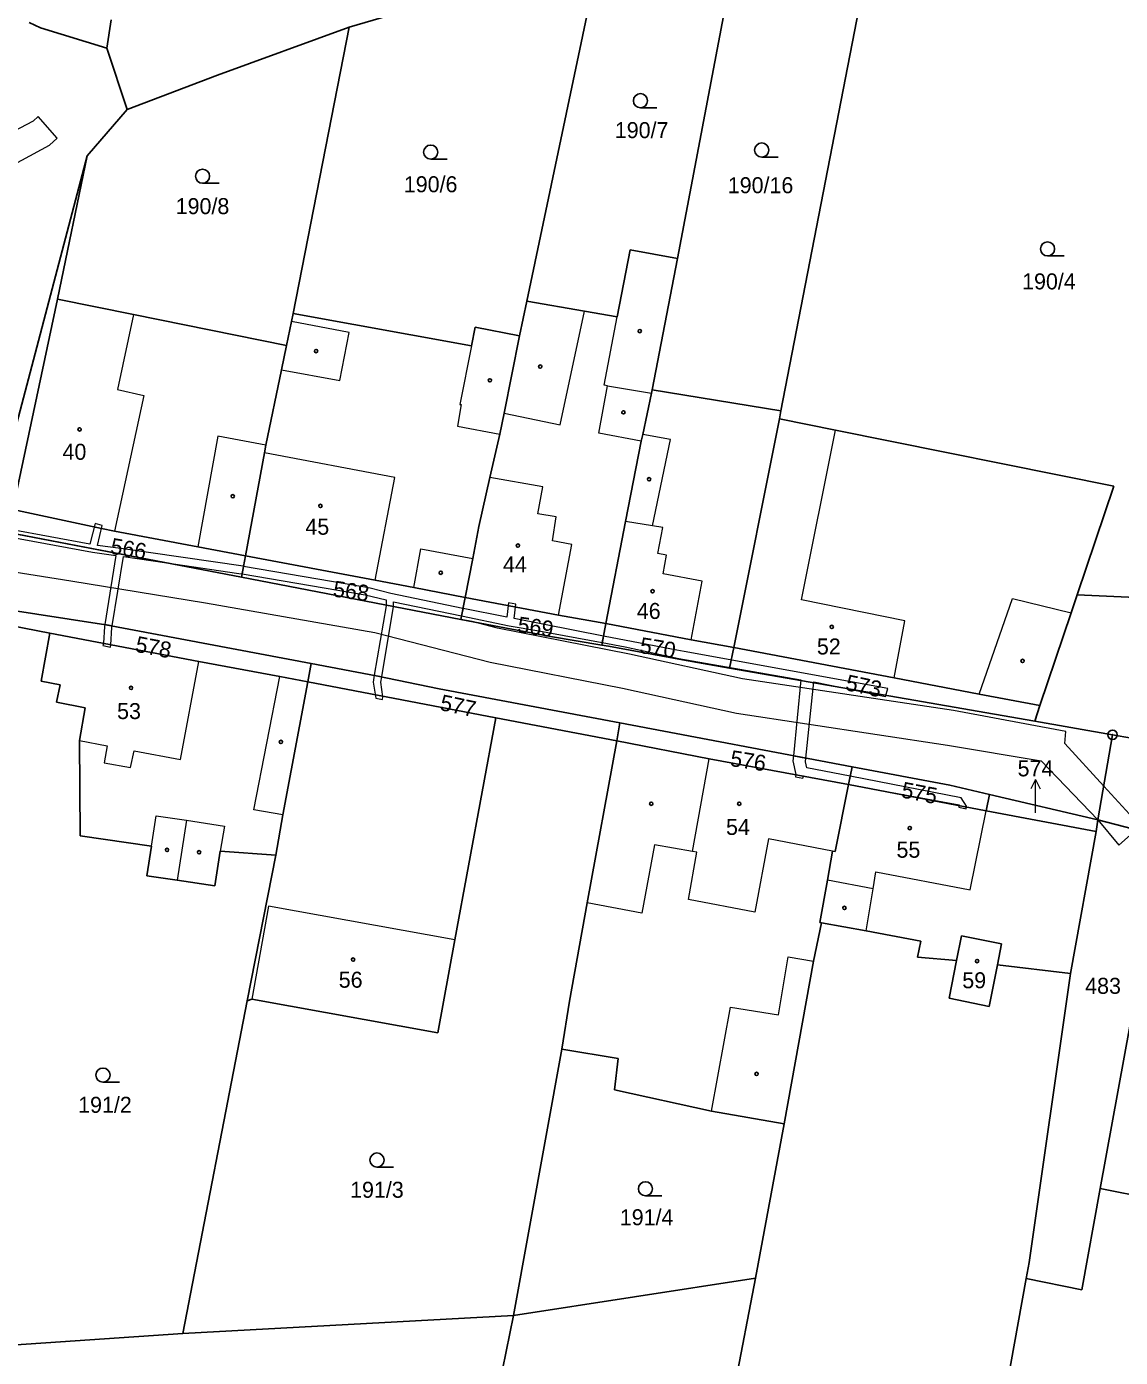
# Model space of a CAD drawing. Extents: x -769392 to -767038, y -1018329 to -1015269.
# Drawn here: x -768383.8 to -768267.7, y -1016351.8 to -1016210.5 of the extents above; entities that cross this region are included whole.
import ezdxf
from ezdxf.enums import TextEntityAlignment as Align

# ---------------------------------------------------------------- set-up
doc = ezdxf.new("R2010")
doc.units = 0
doc.header["$LTSCALE"] = 0.68
for name, color, linetype, lineweight in [('1', 7, 'Continuous', 25), ('13', 7, 'Continuous', 13), ('3', 7, 'Continuous', 25), ('4', 7, 'Continuous', 13), ('5', 7, 'Continuous', 25), ('7', 7, 'Continuous', 13), ('8', 7, 'Continuous', 25)]:
    doc.layers.add(name, color=color, linetype=linetype, lineweight=lineweight)
doc.layers.add('2', color=7, linetype='Continuous')

msp = doc.modelspace()

# ---------------------------------------------------------------- linework, layer by layer
at = {"layer": '1'}
for p, q in [((-768308.37, -1016201.54), (-768314.74, -1016235.08)), ((-768322.98, -1016202.72), (-768349.59, -1016210.55)), ((-768330.71, -1016239.64), (-768322.98, -1016202.72)), ((-768294.39, -1016202.9), (-768303.76, -1016251.27)), ((-768382.33, -1016210.62), (-768383.54, -1016210.03)), ((-768374.85, -1016209.77), (-768375.29, -1016212.76)), ((-768375.29, -1016212.76), (-768382.33, -1016210.62)), ((-768349.59, -1016210.55), (-768363.55, -1016215.62)), ((-768355.52, -1016240.92), (-768349.59, -1016210.55)), ((-768373.13, -1016219.28), (-768375.29, -1016212.76)), ((-768363.55, -1016215.62), (-768373.13, -1016219.28)), ((-768373.13, -1016219.28), (-768377.38, -1016224.21)), ((-768377.38, -1016224.21), (-768387.81, -1016263.79)), ((-768380.52, -1016239.41), (-768377.38, -1016224.21)), ((-768319.76, -1016234.16), (-768321.12, -1016241.28)), ((-768314.74, -1016235.08), (-768319.76, -1016234.16)), ((-768314.74, -1016235.08), (-768317.41, -1016249.05)), ((-768385.26, -1016261.73), (-768380.52, -1016239.41)), ((-768380.52, -1016239.41), (-768372.48, -1016241.04)), ((-768331.5, -1016243.31), (-768330.71, -1016239.64)), ((-768324.62, -1016240.68), (-768330.71, -1016239.64)), ((-768372.48, -1016241.04), (-768356.22, -1016244.34)), ((-768355.69, -1016241.78), (-768355.52, -1016240.92)), ((-768355.52, -1016240.92), (-768336.6, -1016244.38)), ((-768321.12, -1016241.28), (-768324.62, -1016240.68)), ((-768356.22, -1016244.34), (-768355.69, -1016241.78)), ((-768336.6, -1016244.38), (-768336.21, -1016242.38)), ((-768336.21, -1016242.38), (-768331.5, -1016243.31)), ((-768356.22, -1016244.34), (-768356.75, -1016246.91)), ((-768331.5, -1016243.31), (-768333.14, -1016251.52)), ((-768356.75, -1016246.91), (-768358.42, -1016254.92)), ((-768317.48, -1016249.4), (-768318.43, -1016253.78)), ((-768317.41, -1016249.05), (-768317.48, -1016249.4)), ((-768303.76, -1016251.27), (-768317.41, -1016249.05)), ((-768303.76, -1016251.27), (-768303.92, -1016252.12)), ((-768333.14, -1016251.52), (-768333.58, -1016253.73)), ((-768303.92, -1016252.12), (-768308.77, -1016276.41)), ((-768303.92, -1016252.12), (-768297.96, -1016253.32)), ((-768333.58, -1016253.73), (-768334.64, -1016258.34)), ((-768318.43, -1016253.78), (-768318.58, -1016254.49)), ((-768297.96, -1016253.32), (-768268.44, -1016259.26)), ((-768358.42, -1016254.92), (-768358.57, -1016255.72)), ((-768318.58, -1016254.49), (-768320.27, -1016263.01)), ((-768358.57, -1016255.72), (-768360.58, -1016266.67)), ((-768334.64, -1016258.34), (-768335.81, -1016263.56)), ((-768268.44, -1016259.26), (-768272.33, -1016270.82)), ((-768375.87, -1016263.76), (-768385.26, -1016261.73)), ((-768374.47, -1016264.03), (-768375.87, -1016263.76)), ((-768365.62, -1016265.71), (-768374.47, -1016264.03)), ((-768335.81, -1016263.56), (-768336.46, -1016266.94)), ((-768320.27, -1016263.01), (-768322.34, -1016273.86)), ((-768361, -1016268.94), (-768385.75, -1016264.19)), ((-768360.58, -1016266.67), (-768365.62, -1016265.71)), ((-768361, -1016268.94), (-768360.58, -1016266.67)), ((-768346.82, -1016269.26), (-768360.58, -1016266.67)), ((-768336.46, -1016266.94), (-768337.26, -1016271.07)), ((-768337.71, -1016273.41), (-768361, -1016268.94)), ((-768342.7, -1016270.04), (-768346.82, -1016269.26)), ((-768337.26, -1016271.07), (-768342.7, -1016270.04)), ((-768337.71, -1016273.41), (-768337.26, -1016271.07)), ((-768327.37, -1016272.95), (-768337.26, -1016271.07)), ((-768272.97, -1016272.72), (-768272.33, -1016270.82)), ((-768272.33, -1016270.82), (-768252.88, -1016271.66)), ((-768386.61, -1016272.27), (-768375.4, -1016273.98)), ((-768381.35, -1016274.89), (-768387.13, -1016273.73)), ((-768375.4, -1016273.98), (-768353.62, -1016278.09)), ((-768328.21, -1016275.23), (-768337.71, -1016273.41)), ((-768322.34, -1016273.86), (-768327.37, -1016272.95)), ((-768322.78, -1016276.14), (-768322.34, -1016273.86)), ((-768313.27, -1016275.57), (-768322.34, -1016273.86)), ((-768276.27, -1016282.57), (-768272.97, -1016272.72)), ((-768381.35, -1016274.89), (-768382.25, -1016279.96)), ((-768365.54, -1016277.87), (-768381.35, -1016274.89)), ((-768322.78, -1016276.14), (-768328.21, -1016275.23)), ((-768322.07, -1016276.26), (-768322.78, -1016276.14)), ((-768314.21, -1016277.72), (-768322.07, -1016276.26)), ((-768308.77, -1016276.41), (-768313.27, -1016275.57)), ((-768308.77, -1016276.41), (-768309.21, -1016278.59)), ((-768308.77, -1016276.41), (-768291.74, -1016279.61)), ((-768356.95, -1016279.48), (-768365.54, -1016277.87)), ((-768353.62, -1016278.09), (-768353.98, -1016280.04)), ((-768353.62, -1016278.09), (-768346.71, -1016279.39)), ((-768309.21, -1016278.59), (-768314.21, -1016277.72)), ((-768353.98, -1016280.04), (-768356.95, -1016279.48)), ((-768346.71, -1016279.39), (-768340.04, -1016280.77)), ((-768276.82, -1016284.22), (-768309.21, -1016278.59)), ((-768291.74, -1016279.61), (-768282.71, -1016281.35)), ((-768382.25, -1016279.96), (-768380.26, -1016280.37)), ((-768380.26, -1016280.37), (-768380.63, -1016282.2)), ((-768356.61, -1016294.15), (-768353.98, -1016280.04)), ((-768353.98, -1016280.04), (-768334.01, -1016283.86)), ((-768340.04, -1016280.77), (-768320.84, -1016284.4)), ((-768380.63, -1016282.2), (-768377.59, -1016282.81)), ((-768282.71, -1016281.35), (-768276.27, -1016282.57)), ((-768377.59, -1016282.81), (-768378.2, -1016286.27)), ((-768334.01, -1016283.86), (-768338.35, -1016307.43)), ((-768321.19, -1016286.32), (-768334.01, -1016283.86)), ((-768276.82, -1016284.22), (-768276.27, -1016282.57)), ((-768320.84, -1016284.4), (-768321.19, -1016286.32)), ((-768320.84, -1016284.4), (-768296.2, -1016289.06)), ((-768268.57, -1016285.66), (-768276.82, -1016284.22)), ((-768378.2, -1016286.27), (-768378.13, -1016296.38)), ((-768321.19, -1016286.32), (-768324.32, -1016303.49)), ((-768311.36, -1016288.22), (-768321.19, -1016286.32)), ((-768268.57, -1016285.66), (-768270.12, -1016294.69)), ((-768220.34, -1016294.37), (-768268.57, -1016285.66)), ((-768296.58, -1016290.95), (-768311.36, -1016288.22)), ((-768296.2, -1016289.06), (-768296.58, -1016290.95)), ((-768296.2, -1016289.06), (-768285.82, -1016291.02)), ((-768298, -1016298.06), (-768296.58, -1016290.95)), ((-768281.99, -1016293.72), (-768296.58, -1016290.95)), ((-768285.82, -1016291.02), (-768281.64, -1016292)), ((-768281.64, -1016292), (-768281.99, -1016293.72)), ((-768281.64, -1016292), (-768270.12, -1016294.69)), ((-768270.3, -1016295.94), (-768281.99, -1016293.72)), ((-768357.37, -1016298.45), (-768356.61, -1016294.15)), ((-768270.3, -1016295.94), (-768270.12, -1016294.69)), ((-768259.39, -1016297.5), (-768270.12, -1016294.69)), ((-768378.13, -1016296.38), (-768370.54, -1016297.49)), ((-768273.03, -1016311), (-768270.3, -1016295.94)), ((-768370.54, -1016297.49), (-768371.05, -1016300.65)), ((-768363.83, -1016301.69), (-768363.25, -1016298.02)), ((-768363.25, -1016298.02), (-768357.37, -1016298.45)), ((-768298.82, -1016301.09), (-768298.27, -1016298.01)), ((-768298.27, -1016298.01), (-768298, -1016298.06)), ((-768360.39, -1016313.91), (-768357.37, -1016298.45)), ((-768371.05, -1016300.65), (-768367.84, -1016301.11)), ((-768367.84, -1016301.11), (-768363.83, -1016301.69)), ((-768299.62, -1016305.58), (-768298.82, -1016301.09)), ((-768324.32, -1016303.49), (-768326.18, -1016313.96)), ((-768299.46, -1016305.61), (-768300.3, -1016309.68)), ((-768299.46, -1016305.61), (-768299.62, -1016305.58)), ((-768294.72, -1016306.48), (-768299.46, -1016305.61)), ((-768288.9, -1016307.57), (-768294.72, -1016306.48)), ((-768338.35, -1016307.43), (-768340.17, -1016317.32)), ((-768289.26, -1016309.26), (-768288.9, -1016307.57)), ((-768284.59, -1016306.99), (-768285.12, -1016309.64)), ((-768280.37, -1016307.87), (-768284.59, -1016306.99)), ((-768280.79, -1016310.1), (-768280.37, -1016307.87)), ((-768285.12, -1016309.64), (-768289.26, -1016309.26)), ((-768300.3, -1016309.68), (-768303.43, -1016326.96)), ((-768285.12, -1016309.64), (-768285.9, -1016313.61)), ((-768281.66, -1016314.5), (-768280.79, -1016310.1)), ((-768273.03, -1016311), (-768280.79, -1016310.1)), ((-768277.41, -1016341.69), (-768273.03, -1016311)), ((-768266.08, -1016312.93), (-768269.88, -1016333.83)), ((-768367.21, -1016349.21), (-768360.39, -1016313.91)), ((-768359.9, -1016313.74), (-768360.39, -1016313.91)), ((-768340.17, -1016317.32), (-768359.9, -1016313.74)), ((-768326.18, -1016313.96), (-768327.01, -1016319.05)), ((-768285.9, -1016313.61), (-768281.66, -1016314.5)), ((-768327.01, -1016319.05), (-768332.13, -1016347.3)), ((-768321.03, -1016320.03), (-768327.01, -1016319.05)), ((-768321.41, -1016323.34), (-768321.03, -1016320.03)), ((-768311.13, -1016325.63), (-768321.41, -1016323.34)), ((-768303.43, -1016326.96), (-768311.13, -1016325.63)), ((-768306.44, -1016343.34), (-768303.43, -1016326.96)), ((-768136.07, -1016360.95), (-768269.88, -1016333.83)), ((-768277.72, -1016343.38), (-768277.41, -1016341.69)), ((-768332.13, -1016347.3), (-768306.44, -1016343.34)), ((-768306.44, -1016343.34), (-768314.31, -1016383.77)), ((-768291.49, -1016419.17), (-768277.72, -1016343.38)), ((-768332.13, -1016347.3), (-768367.21, -1016349.21)), ((-768346.82, -1016419.68), (-768332.13, -1016347.3)), ((-768367.21, -1016349.21), (-768389.26, -1016350.71))]:
    msp.add_line(p, q, dxfattribs=at)
msp.add_lwpolyline([(-768277.72, -1016343.38), (-768271.84, -1016344.58), (-768269.88, -1016333.83)], dxfattribs=at)
at = {"layer": '13'}
for points in [[(-768388.12, -1016226.71), (-768381.36, -1016223.05), (-768380.55, -1016222.33), (-768382.57, -1016220.03), (-768383.12, -1016220.51), (-768385.18, -1016221.63)], [(-768265.62, -1016295.35), (-768269.5, -1016291.1), (-768273.62, -1016286.59), (-768273.53, -1016285.32), (-768285.46, -1016283.1), (-768307.82, -1016279.73), (-768319.82, -1016277.09), (-768333.82, -1016274.33), (-768336.54, -1016273.63), (-768337.71, -1016273.41), (-768361, -1016268.94), (-768369.19, -1016267.37), (-768384.81, -1016264.37), (-768387.74, -1016263.85), (-768388.8, -1016263.83), (-768395.26, -1016264.06), (-768395.51, -1016264.07), (-768399.68, -1016264.48), (-768411.09, -1016265.88), (-768414.99, -1016266.32), (-768422.34, -1016267.16), (-768438.59, -1016268.98), (-768453.04, -1016270.15)], [(-768449.1, -1016273.07), (-768429.05, -1016271.47), (-768417.15, -1016270.23), (-768402.63, -1016268.55), (-768392.04, -1016267.45), (-768388.19, -1016267.54), (-768385.13, -1016268.37), (-768379.1, -1016269.33), (-768364.82, -1016271.66), (-768346.84, -1016274.82), (-768334.63, -1016277.94), (-768320.58, -1016280.72), (-768308.49, -1016283.37), (-768286.07, -1016286.75), (-768276.15, -1016288.44), (-768270.12, -1016294.69), (-768266.07, -1016295.75)]]:
    msp.add_lwpolyline(points, dxfattribs=at)
for points in [[(-768388.54, -1016263.82), (-768386.79, -1016264.01), (-768385.83, -1016264.62), (-768376.82, -1016266.29), (-768374.34, -1016266.62), (-768375.51, -1016273.96), (-768375.4, -1016273.98), (-768374.73, -1016274.11), (-768373.54, -1016266.73), (-768369.19, -1016267.37), (-768385.75, -1016264.19), (-768387.81, -1016263.79)], [(-768386.47, -1016263.27), (-768387.64, -1016263.14), (-768387.81, -1016263.79), (-768385.75, -1016264.19), (-768369.19, -1016267.37), (-768361.27, -1016268.53), (-768360.93, -1016268.59), (-768360.79, -1016267.78), (-768360.84, -1016267.77), (-768373.79, -1016265.88), (-768376.3, -1016265.55), (-768375.77, -1016263.43), (-768376.53, -1016263.24), (-768377.1, -1016265.43), (-768385.53, -1016263.86)], [(-768360.93, -1016268.59), (-768347.88, -1016270.79), (-768345.66, -1016271.35), (-768345.66, -1016271.96), (-768346.91, -1016279.35), (-768346.71, -1016279.39), (-768346.11, -1016279.51), (-768344.86, -1016272.04), (-768344.86, -1016271.53), (-768337.64, -1016273.04), (-768337.49, -1016272.26), (-768337.53, -1016272.25), (-768345.17, -1016270.65), (-768347.36, -1016270.1), (-768348.14, -1016269.94), (-768360.79, -1016267.78)], [(-768332.61, -1016274.09), (-768329.46, -1016274.62), (-768322.73, -1016275.88), (-768322.59, -1016275.18), (-768332.05, -1016273.32), (-768331.88, -1016271.8), (-768332.66, -1016271.65), (-768332.84, -1016273.17), (-768337.49, -1016272.26), (-768337.64, -1016273.04)], [(-768374.75, -1016274.26), (-768374.73, -1016274.11), (-768375.51, -1016273.96), (-768375.54, -1016274.17), (-768375.64, -1016275.95), (-768375.7, -1016276.2), (-768374.92, -1016276.35), (-768374.86, -1016276.11)], [(-768322.73, -1016275.88), (-768320.3, -1016276.33), (-768314.59, -1016277.58), (-768301.66, -1016279.82), (-768302.43, -1016287.88), (-768301.1, -1016288.13), (-768300.27, -1016280.04), (-768292.65, -1016281.59), (-768292.41, -1016280.74), (-768314.04, -1016276.83), (-768314.82, -1016276.68), (-768322.59, -1016275.18)], [(-768346.21, -1016280.09), (-768346.11, -1016279.51), (-768346.71, -1016279.39), (-768346.91, -1016279.35), (-768347.03, -1016280.09), (-768346.73, -1016281.78), (-768346.05, -1016281.91), (-768346, -1016281.63)], [(-768302.48, -1016288.41), (-768302.17, -1016289.88), (-768302.2, -1016290.13), (-768301.42, -1016290.28), (-768301.37, -1016290.03), (-768296.58, -1016290.95), (-768296.4, -1016290.07), (-768301.02, -1016289.18), (-768301.14, -1016288.55), (-768301.1, -1016288.13), (-768302.43, -1016287.88)], [(-768284.88, -1016293.36), (-768284.1, -1016293.51), (-768284.05, -1016293.25), (-768284.65, -1016292.34), (-768296.4, -1016290.07), (-768296.58, -1016290.95), (-768284.85, -1016293.09)], [(-768267.89, -1016297.39), (-768266.07, -1016295.75), (-768270.12, -1016294.69)]]:
    msp.add_lwpolyline(points, close=True, dxfattribs=at)
at = {"layer": '3'}
for p, q in [((-768318.663, -1016219.09), (-768316.913, -1016219.09)), ((-768340.923, -1016224.55), (-768339.173, -1016224.55)), ((-768305.803, -1016224.33), (-768304.053, -1016224.33)), ((-768365.133, -1016227.11), (-768363.383, -1016227.11)), ((-768275.463, -1016234.83), (-768273.713, -1016234.83)), ((-768375.703, -1016322.54), (-768373.953, -1016322.54)), ((-768346.623, -1016331.56), (-768344.873, -1016331.56)), ((-768318.133, -1016334.61), (-768316.383, -1016334.61))]:
    msp.add_line(p, q, dxfattribs=at)
for centre in [(-768318.6629, -1016218.3398), (-768340.9229, -1016223.7998), (-768305.8029, -1016223.5798), (-768365.1329, -1016226.3598), (-768275.4629, -1016234.0798), (-768375.7029, -1016321.7898), (-768346.6229, -1016330.8098), (-768318.1329, -1016333.8598)]:
    msp.add_circle(centre, 0.75, dxfattribs=at)
at = {"layer": '4'}
for p, q in [((-768372.48, -1016241.04), (-768374.17, -1016249.02)), ((-768327.18, -1016252.75), (-768324.62, -1016240.68)), ((-768322.51, -1016248.55), (-768321.12, -1016241.28)), ((-768349.59, -1016242.95), (-768355.69, -1016241.78)), ((-768350.58, -1016248.06), (-768349.59, -1016242.95)), ((-768336.6, -1016244.38), (-768337.82, -1016250.59)), ((-768356.75, -1016246.91), (-768350.58, -1016248.06)), ((-768322.17, -1016248.6), (-768322.51, -1016248.55)), ((-768371.37, -1016249.63), (-768374.47, -1016264.03)), ((-768374.17, -1016249.02), (-768371.37, -1016249.63)), ((-768323.09, -1016253.65), (-768322.17, -1016248.6)), ((-768322.17, -1016248.6), (-768317.48, -1016249.4)), ((-768337.68, -1016250.61), (-768338.08, -1016252.89)), ((-768337.82, -1016250.59), (-768337.68, -1016250.61)), ((-768333.14, -1016251.52), (-768327.18, -1016252.75)), ((-768363.5, -1016253.96), (-768365.62, -1016265.71)), ((-768358.42, -1016254.92), (-768363.5, -1016253.96)), ((-768338.08, -1016252.89), (-768333.58, -1016253.73)), ((-768318.58, -1016254.49), (-768323.09, -1016253.65)), ((-768315.48, -1016254.3), (-768318.43, -1016253.78)), ((-768301.59, -1016271.34), (-768297.96, -1016253.32)), ((-768317.38, -1016263.47), (-768315.48, -1016254.3)), ((-768344.74, -1016258.34), (-768358.57, -1016255.72)), ((-768346.82, -1016269.26), (-768344.74, -1016258.34)), ((-768329.02, -1016259.32), (-768334.64, -1016258.34)), ((-768329.54, -1016262.22), (-768329.02, -1016259.32)), ((-768327.62, -1016262.54), (-768329.54, -1016262.22)), ((-768327.99, -1016265.06), (-768327.62, -1016262.54)), ((-768317.38, -1016263.47), (-768320.27, -1016263.01)), ((-768316.3, -1016263.65), (-768317.38, -1016263.47)), ((-768316.82, -1016266.43), (-768316.3, -1016263.65)), ((-768325.95, -1016265.45), (-768327.99, -1016265.06)), ((-768327.37, -1016272.95), (-768325.95, -1016265.45)), ((-768342.7, -1016270.04), (-768341.96, -1016265.91)), ((-768341.96, -1016265.91), (-768336.46, -1016266.94)), ((-768315.9, -1016266.61), (-768316.82, -1016266.43)), ((-768316.27, -1016268.58), (-768315.9, -1016266.61)), ((-768312.13, -1016269.36), (-768316.27, -1016268.58)), ((-768313.27, -1016275.57), (-768312.13, -1016269.36)), ((-768282.71, -1016281.35), (-768279.18, -1016271.18)), ((-768279.18, -1016271.18), (-768272.97, -1016272.72)), ((-768290.6, -1016273.55), (-768301.59, -1016271.34)), ((-768291.74, -1016279.61), (-768290.6, -1016273.55)), ((-768367.46, -1016288.29), (-768365.54, -1016277.87)), ((-768359.68, -1016293.64), (-768356.95, -1016279.48)), ((-768378.2, -1016286.27), (-768375.25, -1016286.84)), ((-768375.25, -1016286.84), (-768375.59, -1016288.63)), ((-768372.79, -1016289.15), (-768372.4, -1016287.37)), ((-768372.4, -1016287.37), (-768367.46, -1016288.29)), ((-768375.59, -1016288.63), (-768372.79, -1016289.15)), ((-768313.15, -1016298.05), (-768311.36, -1016288.22)), ((-768356.61, -1016294.15), (-768359.68, -1016293.64)), ((-768283.69, -1016302.12), (-768281.99, -1016293.72)), ((-768370.54, -1016297.49), (-768370.05, -1016294.27)), ((-768370.05, -1016294.27), (-768366.83, -1016294.74)), ((-768366.83, -1016294.74), (-768367.84, -1016301.11)), ((-768366.83, -1016294.74), (-768362.82, -1016295.35)), ((-768362.82, -1016295.35), (-768363.25, -1016298.02)), ((-768317.17, -1016297.33), (-768318.51, -1016304.59)), ((-768313.15, -1016298.05), (-768317.17, -1016297.33)), ((-768305.07, -1016296.7), (-768306.52, -1016304.49)), ((-768298.27, -1016298.01), (-768305.07, -1016296.7)), ((-768313.58, -1016303.16), (-768312.67, -1016298.14)), ((-768312.67, -1016298.14), (-768313.15, -1016298.05)), ((-768293.98, -1016302.03), (-768293.69, -1016300.21)), ((-768293.69, -1016300.21), (-768283.69, -1016302.12)), ((-768293.98, -1016302.03), (-768298.82, -1016301.09)), ((-768294.72, -1016306.48), (-768293.98, -1016302.03)), ((-768318.51, -1016304.59), (-768324.32, -1016303.49)), ((-768306.52, -1016304.49), (-768313.58, -1016303.16)), ((-768358.14, -1016303.86), (-768359.9, -1016313.74)), ((-768338.35, -1016307.43), (-768358.14, -1016303.86)), ((-768304, -1016315.4), (-768302.98, -1016309.24)), ((-768302.98, -1016309.24), (-768300.3, -1016309.68)), ((-768311.13, -1016325.63), (-768309.11, -1016314.57)), ((-768309.11, -1016314.57), (-768304, -1016315.4))]:
    msp.add_line(p, q, dxfattribs=at)
at = {"layer": '5'}
for centre in [(-768318.7368, -1016242.8092), (-768353.0868, -1016244.9192), (-768329.2968, -1016246.5692), (-768334.6368, -1016248.0292), (-768320.4768, -1016251.4292), (-768378.1868, -1016253.2392), (-768317.7468, -1016258.5292), (-768361.9368, -1016260.3292), (-768352.6268, -1016261.3592), (-768331.6768, -1016265.5792), (-768339.8568, -1016268.4592), (-768317.3768, -1016270.4292), (-768298.3668, -1016274.2092), (-768278.1168, -1016277.8192), (-768372.7268, -1016280.6792), (-768356.8168, -1016286.4192), (-768317.5268, -1016292.9892), (-768308.1768, -1016292.9892), (-768290.0868, -1016295.5692), (-768368.9068, -1016297.8792), (-768365.4968, -1016298.1292), (-768297.0268, -1016304.0392), (-768349.1668, -1016309.5292), (-768282.9468, -1016309.6892), (-768306.3468, -1016321.6592)]:
    msp.add_circle(centre, 0.175, dxfattribs=at)
at = {"layer": '7'}
msp.add_line((-768276.75, -1016290.399), (-768277.251, -1016291.4), dxfattribs=at)
msp.add_lwpolyline([(-768276.75, -1016293.95), (-768276.75, -1016293.4), (-768276.75, -1016290.399), (-768276.249, -1016291.4)], dxfattribs=at)
at = {"layer": '8'}
for radius in [0.5, 0.0303]:
    msp.add_circle((-768268.57, -1016285.6599), radius, dxfattribs=at)

# ---------------------------------------------------------------- texts
at = {"layer": '2'}
for s, p in [('190/7', (-768318.54, -1016222.315)), ('190/6', (-768340.93, -1016228.065)), ('190/16', (-768305.92, -1016228.165)), ('190/8', (-768365.14, -1016230.385)), ('190/4', (-768275.32, -1016238.375)), ('40', (-768378.729, -1016256.465)), ('45', (-768352.959, -1016264.425)), ('44', (-768331.989, -1016268.425)), ('46', (-768317.789, -1016273.365)), ('52', (-768298.679, -1016277.135)), ('53', (-768372.939, -1016283.995)), ('574', (-768276.749, -1016290.075)), ('54', (-768308.319, -1016296.295)), ('55', (-768290.229, -1016298.715)), ('56', (-768349.419, -1016312.515)), ('59', (-768283.249, -1016312.575)), ('191/2', (-768375.49, -1016325.795)), ('191/3', (-768346.63, -1016334.815)), ('191/4', (-768318.01, -1016337.735))]:
    msp.add_text(s, height=1.7, dxfattribs=at).set_placement(p, align=Align.CENTER)
for s, rotation, p in [('566', 350, (-768373.1276, -1016266.7516)), ('568', 352, (-768349.4783, -1016271.2386)), ('569', 352, (-768329.9083, -1016275.0486)), ('578', 349, (-768370.4982, -1016277.1929)), ('570', 351, (-768316.949, -1016277.2695)), ('573', 348, (-768295.1372, -1016281.3043)), ('577', 348, (-768338.1872, -1016283.4143)), ('576', 351, (-768307.359, -1016289.2595)), ('575', 349, (-768289.2182, -1016292.6629))]:
    msp.add_text(s, height=1.7, rotation=rotation, dxfattribs=at).set_placement(p, align=Align.CENTER)
msp.add_text('483', height=1.7, dxfattribs=at).set_placement((-768271.47, -1016313.165))

doc.saveas('drawing.dxf')
